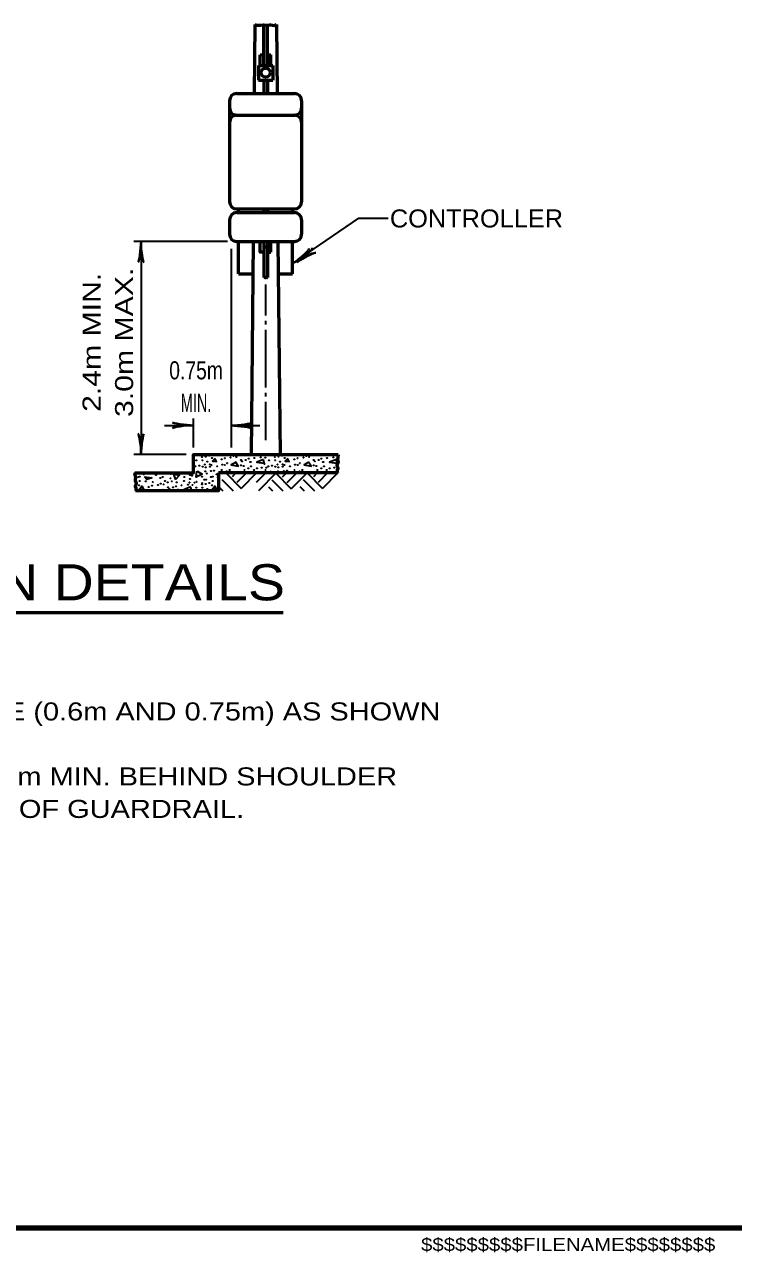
# Model space of a CAD drawing. Extents: x -35 to 821, y -10 to 534.
# Drawn here: x 475.5 to 593.3, y -2.8 to 201.3 of the extents above; entities that cross this region are included whole.
import ezdxf
from ezdxf.enums import TextEntityAlignment as Align

# ---------------------------------------------------------------- set-up
doc = ezdxf.new("R2010")
doc.units = 0
doc.header["$LTSCALE"] = 1.2
doc.layers.add('1', color=7, linetype='Continuous', lineweight=35)

msp = doc.modelspace()

# ---------------------------------------------------------------- linework, layer by layer
at = {"layer": '1', "lineweight": 53}
for p, q in [((513.736, 201.297), (513.622, 189.845)), ((515.236, 194.479), (515.236, 201.254)), ((515.836, 194.479), (515.836, 201.131)), ((517.336, 201.297), (517.449, 189.845)), ((514.636, 194.479), (514.636, 196.279)), ((514.636, 196.279), (515.236, 196.279)), ((515.836, 196.279), (516.436, 196.279)), ((516.436, 194.479), (516.436, 196.279)), ((514.336, 194.479), (516.736, 194.479)), ((514.336, 194.479), (514.336, 192.079)), ((516.736, 194.479), (516.736, 192.079)), ((514.336, 192.079), (516.736, 192.079)), ((515.236, 192.079), (515.236, 189.845)), ((515.836, 192.079), (515.836, 189.845)), ((510.736, 189.845), (520.336, 189.845)), ((509.536, 188.645), (509.536, 171.845)), ((521.536, 188.645), (521.536, 171.845)), ((510.736, 186.245), (520.336, 186.245)), ((510.736, 170.645), (520.336, 170.645)), ((510.736, 170.045), (520.336, 170.045)), ((511.036, 170.045), (511.036, 170.645)), ((515.236, 170.645), (515.236, 170.045)), ((515.836, 170.645), (515.836, 170.045)), ((520.036, 170.045), (520.036, 170.645)), ((509.536, 168.845), (509.536, 166.445)), ((521.536, 168.845), (521.536, 166.445)), ((510.736, 165.245), (520.336, 165.245)), ((511.036, 159.845), (511.036, 165.245)), ((513.486, 165.245), (513.136, 129.821)), ((515.236, 165.245), (515.236, 159.245)), ((515.236, 164.345), (515.836, 164.345)), ((515.836, 165.245), (515.836, 159.245)), ((515.836, 163.445), (516.436, 163.445)), ((516.436, 163.445), (516.436, 165.245)), ((517.585, 165.245), (517.936, 129.821)), ((520.036, 159.845), (520.036, 165.245)), ((511.036, 159.845), (513.433, 159.845)), ((517.638, 159.845), (520.036, 159.845)), ((527.536, 126.821), (507.736, 126.821)), ((403.971, 103.606), (518.449, 103.606))]:
    msp.add_line(p, q, dxfattribs=at)
at = {"layer": '1'}
for p, q in [((509.236, 165.245), (493.636, 165.245)), ((494.836, 165.245), (494.836, 129.821)), ((509.836, 164.045), (509.836, 131.021)), ((515.564, 152.971), (515.564, 158.12)), ((515.564, 151.471), (515.564, 152.071)), ((515.564, 140.971), (515.564, 150.571)), ((515.564, 139.471), (515.564, 140.071)), ((515.564, 132.221), (515.564, 138.571)), ((503.536, 131.021), (503.536, 135.821)), ((498.746, 134.676), (503.546, 134.676)), ((509.772, 134.652), (514.572, 134.652)), ((502.336, 129.821), (493.636, 129.821)), ((508.912, 126.773), (511.48, 124.205)), ((510.616, 126.773), (509.992, 126.149)), ((512.344, 126.773), (510.76, 125.189)), ((514.048, 126.773), (511.48, 124.205)), ((515.584, 126.773), (514, 125.189)), ((517.288, 126.773), (514.336, 123.821)), ((516.18, 126.821), (516.217, 127.081)), ((516.265, 127.057), (516.677, 126.821)), ((517.168, 126.773), (519.808, 124.133)), ((518.992, 126.773), (518.32, 126.077)), ((520.72, 126.773), (519.064, 125.117)), ((522.424, 126.773), (519.808, 124.133)), ((522.424, 126.773), (524.992, 124.205)), ((524.128, 126.773), (523.504, 126.149)), ((525.856, 126.773), (524.272, 125.189)), ((527.56, 126.773), (524.992, 124.205)), ((507.481, 126.121), (507.736, 126.091)), ((507.736, 125.866), (507.481, 126.121)), ((507.736, 124.541), (508.456, 123.821)), ((508.288, 125.693), (510.16, 123.821)), ((516.592, 125.621), (518.411, 123.821)), ((521.248, 124.541), (521.968, 123.821)), ((521.8, 125.693), (523.672, 123.821)), ((498.529, 124.009), (498.185, 123.821)), ((498.617, 123.821), (498.481, 124.033)), ((516.04, 124.469), (516.688, 123.821))]:
    msp.add_line(p, q, dxfattribs=at)
at = {"layer": '1', "lineweight": 158}
msp.add_line((814.384, 1.25), (22.784, 1.25), dxfattribs=at)
at = {"layer": '1', "lineweight": 53}
for points in [[(513.736, 201.297), (514.044, 201.203), (514.683, 201.193), (514.702, 201.193), (515.199, 201.25), (515.331, 201.259), (515.96, 201.174), (516.176, 201.25), (516.41, 201.259), (516.992, 201.146), (517.336, 201.297)], [(515.236, 163.445), (514.636, 163.445), (514.636, 165.245)], [(515.236, 159.245), (515.32, 159.338), (515.464, 159.276), (515.499, 159.276), (515.615, 159.276), (515.657, 159.29), (515.732, 159.29), (515.801, 159.234), (515.836, 159.245)], [(493.936, 123.821), (494.045, 123.979), (494.051, 124.234), (493.921, 124.529), (493.94, 124.699), (494.078, 125.026), (493.927, 125.439), (493.894, 125.628), (493.96, 126.034), (493.94, 126.224), (493.803, 126.479), (493.936, 126.821), (503.536, 126.821), (503.536, 129.821), (527.593, 129.821)], [(527.593, 129.821), (527.512, 129.034), (527.577, 128.628), (527.544, 128.439), (527.394, 128.026), (527.531, 127.699), (527.551, 127.529), (527.42, 127.234), (527.427, 126.979), (527.536, 126.821)], [(507.736, 126.821), (507.736, 123.821), (493.936, 123.821)]]:
    msp.add_lwpolyline(points, dxfattribs=at)
at = {"layer": '1'}
for points in [[(520.188, 161.684), (531.06, 169.138), (535.924, 169.138)], [(507.145, 129.193), (506.689, 128.713), (507.385, 128.665), (507.145, 129.145)], [(510.625, 128.569), (509.833, 128.137), (511.009, 127.921), (510.577, 128.593)], [(515.209, 129.025), (514.081, 128.569), (515.329, 128.425), (515.209, 128.977)], [(519.241, 129.193), (518.785, 128.713), (519.481, 128.665), (519.241, 129.145)], [(522.721, 128.569), (521.929, 128.137), (523.105, 127.921), (522.673, 128.593)], [(527.305, 129.025), (526.177, 128.569), (527.425, 128.425), (527.305, 128.977)], [(500.593, 125.617), (500.305, 126.577), (501.241, 126.385), (500.569, 125.665)], [(504.169, 127.057), (505.009, 126.577), (503.977, 126.073), (504.121, 127.081)], [(495.049, 124.633), (494.593, 124.153), (495.289, 124.105), (495.049, 124.585)], [(507.145, 124.633), (506.689, 124.153), (507.385, 124.105), (507.145, 124.585)], [(503.113, 124.465), (501.985, 124.009), (503.233, 123.865), (503.113, 124.417)]]:
    msp.add_lwpolyline(points, dxfattribs=at)
msp.add_lwpolyline([(495.385, 126.121), (496.633, 125.977), (495.817, 125.689)], close=True, dxfattribs=at)
at = {"layer": '1', "lineweight": 53}
msp.add_circle((515.55, 193.291), 0.75, dxfattribs=at)
at = {"layer": '1'}
for centre in [(503.728, 129.717), (504.03, 128.88), (504.984, 129.436), (505, 129.637), (505.032, 128.896), (505.588, 129.5), (505.843, 128.673), (506.177, 129.653), (506.616, 129.277), (508.222, 129.023), (508.763, 129.23), (509.733, 129.341), (510.21, 129.574), (510.687, 129.421), (511.355, 129.765), (511.434, 128.943), (511.625, 128.689), (512.245, 128.943), (512.723, 129.134), (512.834, 129.765), (512.993, 128.577), (513.057, 128.577), (513.661, 129.261), (514.726, 129.373), (514.981, 129.749), (515.49, 129.325), (515.824, 129.717), (516.126, 128.88), (517.08, 129.436), (517.096, 129.637), (517.128, 128.896), (517.684, 129.5), (517.939, 128.673), (518.273, 129.653), (518.712, 129.277), (520.318, 129.023), (520.859, 129.23), (521.829, 129.341), (522.306, 129.574), (522.783, 129.421), (523.451, 129.765), (523.53, 128.943), (523.721, 128.689), (524.341, 128.943), (524.819, 129.134), (524.93, 129.765), (525.089, 128.577), (525.153, 128.577), (525.757, 129.261), (526.822, 129.373), (527.077, 129.749), (495.283, 126.541), (498.368, 126.684), (499.784, 126.605), (503.887, 127.861), (504.523, 128.005), (505.064, 127.83), (505.445, 128.18), (505.509, 127.034), (505.573, 127.702), (505.779, 126.684), (506.272, 128.196), (506.288, 127.814), (506.479, 127.098), (506.552, 128.1), (506.981, 127.161), (507.379, 126.541), (507.49, 127.893), (508.254, 127.289), (508.349, 128.164), (508.763, 128.116), (509.081, 127.034), (509.144, 128.402), (509.558, 127.289), (510.957, 126.891), (511.434, 128.052), (511.896, 127.941), (512.039, 127.257), (512.691, 127.543), (513.136, 127.877), (513.613, 127.289), (514.106, 127.559), (514.885, 127.671), (515.363, 128.259), (515.442, 126.907), (515.522, 127.273), (515.649, 127.655), (515.983, 127.861), (516.619, 128.005), (517.16, 127.83), (517.541, 128.18), (517.605, 127.034), (517.669, 127.702), (518.368, 128.196), (518.384, 127.814), (518.575, 127.098), (518.648, 128.1), (519.077, 127.161), (519.586, 127.893), (520.35, 127.289), (520.445, 128.164), (520.859, 128.116), (521.177, 127.034), (521.24, 128.402), (521.654, 127.289), (523.053, 126.891), (523.53, 128.052), (523.992, 127.941), (524.135, 127.257), (524.787, 127.543), (525.232, 127.877), (525.709, 127.289), (526.202, 127.559), (526.981, 127.671), (494.081, 125.093), (494.359, 126.125), (494.52, 124.717), (494.631, 126.143), (494.631, 125.427), (495.601, 125.38), (496.126, 124.463), (496.667, 124.67), (496.794, 125.284), (497.319, 126.414), (497.637, 124.781), (498.034, 125.921), (498.114, 125.014), (498.416, 126.096), (498.591, 124.861), (498.829, 125.443), (499.259, 125.205), (499.736, 125.889), (499.959, 125.38), (500.627, 124.574), (500.738, 125.205), (501.565, 124.701), (501.962, 125.459), (502.042, 126.112), (502.63, 124.813), (502.885, 125.189), (502.98, 126.414), (502.996, 125.793), (503.33, 126.334), (503.394, 124.765), (503.728, 125.157), (504.062, 125.3), (504.952, 126.159), (504.984, 124.876), (505, 125.077), (505.35, 125.682), (505.588, 124.94), (505.62, 125.682), (506.177, 125.093), (506.455, 126.125), (506.616, 124.717), (506.727, 126.143), (506.727, 125.427), (507.697, 125.38), (499.338, 124.383), (499.529, 124.129), (500.149, 124.383), (500.897, 124.017), (500.961, 124.017), (504.03, 124.32), (505.032, 124.336), (505.843, 124.113)]:
    msp.add_circle(centre, 0.0318, dxfattribs=at)
at = {"layer": '1', "lineweight": 53}
for centre, start, end in [((510.736, 188.645), 90, 180), ((520.336, 188.645), 0, 90), ((510.736, 187.445), 180, 270), ((510.736, 185.045), 90, 180), ((520.336, 187.445), 270, 0), ((520.336, 185.045), 0, 90), ((510.736, 171.845), 180, 270), ((520.336, 171.845), 270, 0), ((510.736, 168.845), 90, 180), ((520.336, 168.845), 0, 90), ((510.736, 166.445), 180, 270), ((520.336, 166.445), 270, 0)]:
    msp.add_arc(centre, 1.2, start, end, dxfattribs=at)
at = {"layer": '1'}
for centre, start, end in [((508.89, 129.844), 226.35082, 313.64918), ((520.986, 129.844), 226.35082, 313.64918), ((527.586, 129.325), 61.61934, 241.7845), ((496.094, 126.811), 162.01481, 17.98519), ((501.851, 126.843), 223.9797, 316.0203), ((502.471, 126.811), 162.01481, 17.98519), ((503.553, 127.655), 237.37076, 122.62924), ((508.19, 126.811), 17.98519, 162.01481), ((513.947, 126.843), 316.0203, 223.9797), ((514.567, 126.811), 17.98519, 162.01481), ((520.286, 126.811), 17.98519, 162.01481), ((526.043, 126.843), 316.0203, 223.9797), ((526.663, 126.811), 17.98519, 162.01481), ((527.459, 128.259), 32.83014, 287.06312), ((497.048, 123.842), 318.30023, 221.69977)]:
    msp.add_arc(centre, 0.0318, start, end, dxfattribs=at)
at = {"layer": '1', "lineweight": 40}
for centre, major_axis, ratio, start_param, end_param in [((494.582, 163.901), (0.211, 2.108), 0.07063, 3.1407148, 5.41811), ((494.582, 163.901), (0.211, 2.108), 0.07063, 3.1407148, 5.41811), ((495.167, 163.936), (-0.187, 2.143), 0.122415, 0.8963533, 3.1415927), ((495.167, 163.936), (-0.187, 2.143), 0.122415, 0.8963533, 3.1415927), ((521.095, 162.696), (-1.661, -1.366), 0.122415, 0.8963533, 3.1415927), ((521.455, 162.233), (1.858, 1.018), 0.07063, 6.2823074, 8.5597026), ((521.649, 162.829), (-1.661, -1.366), 0.122415, 0.8963533, 3.1415927), ((522.01, 162.366), (1.858, 1.018), 0.07063, 6.2823074, 8.5597026), ((502.19, 134.94), (2.108, -0.211), 0.07063, 3.1407148, 5.41811), ((511.082, 134.984), (-2.143, -0.187), 0.122415, 0.8963533, 3.1415927), ((511.082, 134.984), (-2.143, -0.187), 0.122415, 0.8963533, 3.1415927), ((494.504, 131.131), (0.187, -2.143), 0.122415, 0.8963533, 3.1415927), ((495.09, 131.166), (-0.211, -2.108), 0.07063, 3.1407148, 5.41811), ((502.226, 134.354), (2.143, 0.187), 0.122415, 0.8963533, 3.1415927), ((511.117, 134.398), (-2.108, 0.211), 0.07063, 3.1407148, 5.41811), ((511.117, 134.398), (-2.108, 0.211), 0.07063, 3.1407148, 5.41811)]:
    msp.add_ellipse(centre, major_axis=major_axis, ratio=ratio, start_param=start_param, end_param=end_param, dxfattribs=at)

# ---------------------------------------------------------------- texts
at = {"layer": '1'}
for s, height, width, p in [('CONTROLLER', 3, 1.05, (536.198, 167.574)), ('SIGN LOCATION DETAILS', 6, 1.15, (405.456, 105.603)), ('HORIZONTAL MINIMUM CLEARANCE (0.6m AND 0.75m) AS SHOWN', 3, 1.2, (390.808, 85.642)), ('FOR RURAL AREAS IT SHALL BE 1.2m MIN. BEHIND SHOULDER', 3, 1.2, (390.808, 74.842)), ('EDGE AND 0.6m MIN. BEHIND FACE OF GUARDRAIL.', 3, 1.2, (390.808, 69.442)), ('$$$$$$$$$FILENAME$$$$$$$$', 2.2, 1.15, (541.384, -2.55))]:
    msp.add_text(s, height=height, dxfattribs=dict(at, width=width)).set_placement(p)
at = {"layer": '1', "width": 1.25}
for s, p in [('2.4m MIN.', (488.119, 148.482)), ('3.0m MAX.', (493.519, 148.482))]:
    msp.add_text(s, height=3, rotation=90, dxfattribs=at).set_placement(p, align=Align.CENTER)
at = {"layer": '1'}
for s, width, p in [('0.75m', 0.8, (503.984, 142.33)), ('MIN.', 0.6, (503.984, 136.93))]:
    msp.add_text(s, height=3, dxfattribs=dict(at, width=width)).set_placement(p, align=Align.CENTER)

doc.saveas('drawing.dxf')
